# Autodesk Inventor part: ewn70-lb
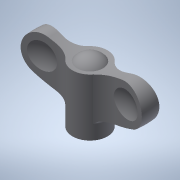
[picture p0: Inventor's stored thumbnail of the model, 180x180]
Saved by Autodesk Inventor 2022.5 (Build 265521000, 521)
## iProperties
Created: 2016-12
Part Number: ewn70-lb
Material: 一般
Document SubType Name: Modeling
Designer: imaocorp
Density: 1 g/cm^3
Appearance: 既定
Author: imaocorp
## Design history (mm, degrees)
node "ewn70-lb.x_t1"
node "ewn70-lb"
node "Base1"
